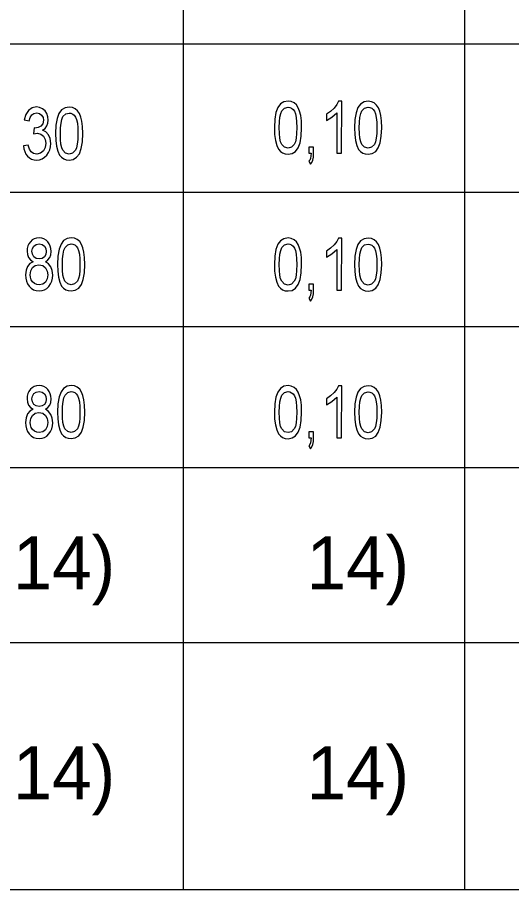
# Model space of a CAD drawing. Extents: x -480568.5 to -480543.1, y -1126945.4 to -1126930.6.
# Drawn here: x -480548.039 to -480547.136, y -1126935.259 to -1126933.667 of the extents above; entities that cross this region are included whole.
import ezdxf

# ---------------------------------------------------------------- set-up
doc = ezdxf.new("R2010")
doc.units = 0
doc.layers.add('detaily', color=7, linetype='Continuous')
doc.layers.add('EL1', color=7, linetype='Continuous')

msp = doc.modelspace()

# ---------------------------------------------------------------- linework, layer by layer
at = {"layer": 'detaily'}
msp.add_lwpolyline([(-480551.8459, -1126935.2592), (-480543.5956, -1126935.2592), (-480543.5956, -1126932.0257), (-480551.8459, -1126932.0257)], close=True, dxfattribs=at)
at = {"layer": 'EL1'}
for p, q in [((-480547.222, -1126932.0257), (-480547.222, -1126935.2588)), ((-480547.7355, -1126935.2588), (-480547.7355, -1126932.3243)), ((-480550.8407, -1126933.7155), (-480543.5956, -1126933.7155)), ((-480549.8036, -1126933.9862), (-480543.5956, -1126933.9862)), ((-480550.8351, -1126934.2311), (-480543.5956, -1126934.2311)), ((-480543.5956, -1126934.4894), (-480551.8459, -1126934.4894)), ((-480543.5956, -1126934.8085), (-480551.8459, -1126934.8085))]:
    msp.add_line(p, q, dxfattribs=at)
for points in [[(-480547.5692, -1126933.8683), (-480547.5688, -1126933.8808), (-480547.5674, -1126933.8915), (-480547.565, -1126933.9006), (-480547.5617, -1126933.9078), (-480547.5583, -1126933.9117), (-480547.5543, -1126933.9145), (-480547.5497, -1126933.9162), (-480547.5444, -1126933.9167), (-480547.5368, -1126933.9154), (-480547.5306, -1126933.9116), (-480547.5258, -1126933.9051), (-480547.5223, -1126933.8958), (-480547.5203, -1126933.8836), (-480547.5195, -1126933.8684), (-480547.5199, -1126933.8557), (-480547.5212, -1126933.846), (-480547.5232, -1126933.8383), (-480547.5256, -1126933.8319), (-480547.5288, -1126933.8268), (-480547.5332, -1126933.823), (-480547.5385, -1126933.8207), (-480547.5443, -1126933.8199), (-480547.5519, -1126933.8212), (-480547.5581, -1126933.825), (-480547.5629, -1126933.8315), (-480547.5664, -1126933.8408), (-480547.5685, -1126933.853)], [(-480547.4464, -1126933.915), (-480547.4463, -1126933.82), (-480547.452, -1126933.82), (-480547.4553, -1126933.8263), (-480547.4603, -1126933.8327), (-480547.4667, -1126933.8387), (-480547.4741, -1126933.8437), (-480547.4741, -1126933.855), (-480547.4641, -1126933.849), (-480547.4551, -1126933.841), (-480547.4552, -1126933.915)], [(-480547.4229, -1126933.8685), (-480547.4225, -1126933.881), (-480547.4211, -1126933.8917), (-480547.4188, -1126933.9008), (-480547.4155, -1126933.908), (-480547.4121, -1126933.9119), (-480547.408, -1126933.9147), (-480547.4034, -1126933.9164), (-480547.3982, -1126933.9169), (-480547.3905, -1126933.9156), (-480547.3843, -1126933.9118), (-480547.3795, -1126933.9053), (-480547.376, -1126933.896), (-480547.374, -1126933.8838), (-480547.3732, -1126933.8686), (-480547.3737, -1126933.8559), (-480547.3749, -1126933.8462), (-480547.3769, -1126933.8385), (-480547.3793, -1126933.832), (-480547.3825, -1126933.827), (-480547.3869, -1126933.8232), (-480547.3922, -1126933.8209), (-480547.398, -1126933.8201), (-480547.4056, -1126933.8214), (-480547.4118, -1126933.8252), (-480547.4167, -1126933.8317), (-480547.4201, -1126933.841), (-480547.4222, -1126933.8532)], [(-480548.0275, -1126933.9018), (-480548.0267, -1126933.9072), (-480548.0252, -1126933.9121), (-480548.023, -1126933.9165), (-480548.02, -1126933.9203), (-480548.0165, -1126933.9234), (-480548.0126, -1126933.9256), (-480548.0082, -1126933.927), (-480548.0034, -1126933.9274), (-480547.9982, -1126933.9269), (-480547.9934, -1126933.9252), (-480547.989, -1126933.9225), (-480547.9851, -1126933.9186), (-480547.982, -1126933.9139), (-480547.9797, -1126933.9088), (-480547.9783, -1126933.9031), (-480547.9778, -1126933.897), (-480547.9788, -1126933.8884), (-480547.9819, -1126933.8813), (-480547.9866, -1126933.8761), (-480547.9926, -1126933.873), (-480547.9881, -1126933.8696), (-480547.9848, -1126933.8653), (-480547.9828, -1126933.8601), (-480547.9822, -1126933.8544), (-480547.9828, -1126933.8484), (-480547.9848, -1126933.8426), (-480547.9881, -1126933.8377), (-480547.9926, -1126933.8338), (-480547.998, -1126933.8314), (-480548.0038, -1126933.8306), (-480548.0118, -1126933.8321), (-480548.0184, -1126933.8368), (-480548.0233, -1126933.8443), (-480548.026, -1126933.8543), (-480548.0172, -1126933.8561), (-480548.0155, -1126933.8498), (-480548.0125, -1126933.8452), (-480548.0084, -1126933.8425), (-480548.0034, -1126933.8415), (-480547.9984, -1126933.8425), (-480547.9944, -1126933.8453), (-480547.9918, -1126933.8496), (-480547.9909, -1126933.8549), (-480547.9922, -1126933.8612), (-480547.9957, -1126933.8656), (-480548.0008, -1126933.8682), (-480548.0065, -1126933.8691), (-480548.0081, -1126933.8689), (-480548.0092, -1126933.8799), (-480548.0022, -1126933.8786), (-480547.996, -1126933.88), (-480547.991, -1126933.8838), (-480547.9877, -1126933.8897), (-480547.9866, -1126933.8969), (-480547.9877, -1126933.9045), (-480547.991, -1126933.9108), (-480547.9963, -1126933.9151), (-480548.0031, -1126933.9165), (-480548.009, -1126933.9155), (-480548.0134, -1126933.9126), (-480548.0166, -1126933.9075), (-480548.0188, -1126933.9)], [(-480547.969, -1126933.8791), (-480547.9685, -1126933.8916), (-480547.9671, -1126933.9023), (-480547.9648, -1126933.9113), (-480547.9615, -1126933.9186), (-480547.9581, -1126933.9225), (-480547.9541, -1126933.9253), (-480547.9494, -1126933.9269), (-480547.9442, -1126933.9275), (-480547.9366, -1126933.9262), (-480547.9304, -1126933.9224), (-480547.9255, -1126933.9159), (-480547.9221, -1126933.9065), (-480547.92, -1126933.8943), (-480547.9193, -1126933.8791), (-480547.9197, -1126933.8665), (-480547.921, -1126933.8567), (-480547.9229, -1126933.8491), (-480547.9253, -1126933.8426), (-480547.9286, -1126933.8375), (-480547.933, -1126933.8338), (-480547.9382, -1126933.8314), (-480547.9441, -1126933.8307), (-480547.9517, -1126933.8319), (-480547.9579, -1126933.8357), (-480547.9627, -1126933.8423), (-480547.9662, -1126933.8516), (-480547.9683, -1126933.8638)], [(-480547.9602, -1126933.8791), (-480547.9599, -1126933.8687), (-480547.959, -1126933.8601), (-480547.9575, -1126933.8533), (-480547.9554, -1126933.8482), (-480547.9504, -1126933.8433), (-480547.9442, -1126933.8416), (-480547.9408, -1126933.8421), (-480547.9376, -1126933.8435), (-480547.9349, -1126933.8458), (-480547.9325, -1126933.8491), (-480547.9306, -1126933.8537), (-480547.9291, -1126933.8603), (-480547.9283, -1126933.8688), (-480547.9281, -1126933.8791), (-480547.9284, -1126933.8898), (-480547.9292, -1126933.8984), (-480547.9307, -1126933.905), (-480547.9327, -1126933.9095), (-480547.9379, -1126933.9148), (-480547.9442, -1126933.9165), (-480547.9505, -1126933.9148), (-480547.9556, -1126933.9095), (-480547.9577, -1126933.905), (-480547.9591, -1126933.8984), (-480547.9599, -1126933.8898)], [(-480547.5604, -1126933.8683), (-480547.5602, -1126933.8579), (-480547.5593, -1126933.8493), (-480547.5578, -1126933.8425), (-480547.5557, -1126933.8374), (-480547.5507, -1126933.8325), (-480547.5444, -1126933.8309), (-480547.541, -1126933.8314), (-480547.5379, -1126933.8327), (-480547.5351, -1126933.8351), (-480547.5327, -1126933.8383), (-480547.5308, -1126933.843), (-480547.5294, -1126933.8495), (-480547.5286, -1126933.858), (-480547.5283, -1126933.8683), (-480547.5286, -1126933.879), (-480547.5295, -1126933.8877), (-480547.531, -1126933.8943), (-480547.533, -1126933.8988), (-480547.5382, -1126933.904), (-480547.5444, -1126933.9058), (-480547.5507, -1126933.904), (-480547.5559, -1126933.8988), (-480547.5579, -1126933.8942), (-480547.5593, -1126933.8876), (-480547.5602, -1126933.879)], [(-480547.4142, -1126933.8685), (-480547.4139, -1126933.8581), (-480547.413, -1126933.8495), (-480547.4115, -1126933.8427), (-480547.4094, -1126933.8376), (-480547.4044, -1126933.8327), (-480547.3982, -1126933.831), (-480547.3947, -1126933.8315), (-480547.3916, -1126933.8329), (-480547.3888, -1126933.8353), (-480547.3864, -1126933.8385), (-480547.3845, -1126933.8432), (-480547.3831, -1126933.8497), (-480547.3823, -1126933.8582), (-480547.382, -1126933.8685), (-480547.3823, -1126933.8792), (-480547.3832, -1126933.8878), (-480547.3847, -1126933.8944), (-480547.3867, -1126933.899), (-480547.3919, -1126933.9042), (-480547.3981, -1126933.906), (-480547.4044, -1126933.9042), (-480547.4096, -1126933.8989), (-480547.4116, -1126933.8944), (-480547.4131, -1126933.8878), (-480547.4139, -1126933.8792)], [(-480547.5064, -1126933.9149), (-480547.502, -1126933.915), (-480547.5032, -1126933.9245), (-480547.5045, -1126933.9274), (-480547.5064, -1126933.9296), (-480547.5035, -1126933.935), (-480547.5009, -1126933.9319), (-480547.499, -1126933.9276), (-480547.498, -1126933.922), (-480547.4976, -1126933.915), (-480547.4976, -1126933.904), (-480547.5064, -1126933.904)], [(-480548.0101, -1126934.113), (-480548.0159, -1126934.1162), (-480548.0203, -1126934.1215), (-480548.0229, -1126934.1285), (-480548.0238, -1126934.1371), (-480548.0234, -1126934.1431), (-480548.0221, -1126934.1485), (-480548.02, -1126934.1535), (-480548.017, -1126934.1579), (-480548.0134, -1126934.1616), (-480548.0091, -1126934.1642), (-480548.0044, -1126934.1658), (-480547.999, -1126934.1663), (-480547.9937, -1126934.1658), (-480547.9889, -1126934.1642), (-480547.9847, -1126934.1617), (-480547.981, -1126934.158), (-480547.978, -1126934.1536), (-480547.9759, -1126934.1487), (-480547.9746, -1126934.1433), (-480547.9741, -1126934.1375), (-480547.975, -1126934.1292), (-480547.9775, -1126934.1222), (-480547.9818, -1126934.1167), (-480547.9875, -1126934.113), (-480547.9829, -1126934.1098), (-480547.9796, -1126934.1055), (-480547.9777, -1126934.1002), (-480547.977, -1126934.0941), (-480547.9774, -1126934.0892), (-480547.9785, -1126934.0846), (-480547.9804, -1126934.0804), (-480547.983, -1126934.0766), (-480547.9863, -1126934.0735), (-480547.9901, -1126934.0713), (-480547.9943, -1126934.0699), (-480547.999, -1126934.0695), (-480548.0038, -1126934.0699), (-480548.008, -1126934.0712), (-480548.0117, -1126934.0734), (-480548.0149, -1126934.0765), (-480548.0175, -1126934.0802), (-480548.0194, -1126934.0843), (-480548.0205, -1126934.0888), (-480548.0209, -1126934.0937), (-480548.0202, -1126934.1001), (-480548.0182, -1126934.1054), (-480548.0149, -1126934.1098)], [(-480548.0121, -1126934.0937), (-480548.0112, -1126934.0887), (-480548.0087, -1126934.0844), (-480548.0046, -1126934.0814), (-480547.9989, -1126934.0804), (-480547.9933, -1126934.0815), (-480547.9892, -1126934.0845), (-480547.9866, -1126934.089), (-480547.9858, -1126934.0944), (-480547.9866, -1126934.0996), (-480547.9891, -1126934.104), (-480547.9932, -1126934.1069), (-480547.9988, -1126934.1078), (-480548.0046, -1126934.1069), (-480548.0088, -1126934.1039), (-480548.0113, -1126934.0994)], [(-480547.9653, -1126934.1179), (-480547.9648, -1126934.1304), (-480547.9634, -1126934.1412), (-480547.9611, -1126934.1502), (-480547.9578, -1126934.1574), (-480547.9544, -1126934.1613), (-480547.9504, -1126934.1641), (-480547.9457, -1126934.1658), (-480547.9405, -1126934.1664), (-480547.9329, -1126934.1651), (-480547.9267, -1126934.1612), (-480547.9218, -1126934.1547), (-480547.9184, -1126934.1454), (-480547.9163, -1126934.1332), (-480547.9156, -1126934.118), (-480547.916, -1126934.1054), (-480547.9173, -1126934.0956), (-480547.9192, -1126934.0879), (-480547.9216, -1126934.0815), (-480547.9249, -1126934.0764), (-480547.9293, -1126934.0726), (-480547.9345, -1126934.0703), (-480547.9404, -1126934.0695), (-480547.948, -1126934.0708), (-480547.9542, -1126934.0746), (-480547.959, -1126934.0812), (-480547.9625, -1126934.0904), (-480547.9646, -1126934.1027)], [(-480547.9565, -1126934.1179), (-480547.9562, -1126934.1076), (-480547.9553, -1126934.099), (-480547.9538, -1126934.0922), (-480547.9517, -1126934.0871), (-480547.9467, -1126934.0822), (-480547.9405, -1126934.0805), (-480547.9371, -1126934.081), (-480547.9339, -1126934.0824), (-480547.9312, -1126934.0847), (-480547.9288, -1126934.0879), (-480547.9269, -1126934.0926), (-480547.9254, -1126934.0992), (-480547.9246, -1126934.1076), (-480547.9244, -1126934.118), (-480547.9247, -1126934.1287), (-480547.9255, -1126934.1373), (-480547.927, -1126934.1439), (-480547.929, -1126934.1484), (-480547.9342, -1126934.1537), (-480547.9405, -1126934.1554), (-480547.9468, -1126934.1537), (-480547.9519, -1126934.1484), (-480547.954, -1126934.1439), (-480547.9554, -1126934.1373), (-480547.9562, -1126934.1287)], [(-480547.5692, -1126934.1181), (-480547.5688, -1126934.1306), (-480547.5674, -1126934.1414), (-480547.565, -1126934.1504), (-480547.5617, -1126934.1576), (-480547.5583, -1126934.1615), (-480547.5543, -1126934.1643), (-480547.5497, -1126934.166), (-480547.5444, -1126934.1665), (-480547.5368, -1126934.1653), (-480547.5306, -1126934.1614), (-480547.5258, -1126934.1549), (-480547.5223, -1126934.1456), (-480547.5203, -1126934.1334), (-480547.5195, -1126934.1182), (-480547.5199, -1126934.1056), (-480547.5212, -1126934.0958), (-480547.5232, -1126934.0881), (-480547.5256, -1126934.0817), (-480547.5288, -1126934.0766), (-480547.5332, -1126934.0728), (-480547.5385, -1126934.0705), (-480547.5443, -1126934.0697), (-480547.5519, -1126934.071), (-480547.5581, -1126934.0748), (-480547.5629, -1126934.0813), (-480547.5664, -1126934.0906), (-480547.5685, -1126934.1029)], [(-480547.5604, -1126934.1181), (-480547.5602, -1126934.1077), (-480547.5593, -1126934.0992), (-480547.5578, -1126934.0923), (-480547.5557, -1126934.0872), (-480547.5507, -1126934.0823), (-480547.5444, -1126934.0807), (-480547.541, -1126934.0812), (-480547.5379, -1126934.0825), (-480547.5351, -1126934.0849), (-480547.5327, -1126934.0881), (-480547.5308, -1126934.0928), (-480547.5294, -1126934.0993), (-480547.5286, -1126934.1078), (-480547.5283, -1126934.1182), (-480547.5286, -1126934.1289), (-480547.5295, -1126934.1375), (-480547.531, -1126934.1441), (-480547.533, -1126934.1486), (-480547.5382, -1126934.1539), (-480547.5444, -1126934.1556), (-480547.5507, -1126934.1538), (-480547.5559, -1126934.1486), (-480547.5579, -1126934.1441), (-480547.5593, -1126934.1375), (-480547.5602, -1126934.1288)], [(-480547.4464, -1126934.1648), (-480547.4463, -1126934.0698), (-480547.452, -1126934.0698), (-480547.4553, -1126934.0761), (-480547.4603, -1126934.0825), (-480547.4667, -1126934.0885), (-480547.4741, -1126934.0936), (-480547.4741, -1126934.1048), (-480547.4641, -1126934.0988), (-480547.4551, -1126934.0908), (-480547.4552, -1126934.1648)], [(-480547.4229, -1126934.1183), (-480547.4225, -1126934.1308), (-480547.4211, -1126934.1416), (-480547.4188, -1126934.1506), (-480547.4155, -1126934.1578), (-480547.4121, -1126934.1617), (-480547.408, -1126934.1645), (-480547.4034, -1126934.1662), (-480547.3982, -1126934.1667), (-480547.3905, -1126934.1654), (-480547.3843, -1126934.1616), (-480547.3795, -1126934.1551), (-480547.376, -1126934.1458), (-480547.374, -1126934.1336), (-480547.3732, -1126934.1184), (-480547.3737, -1126934.1057), (-480547.3749, -1126934.096), (-480547.3769, -1126934.0883), (-480547.3793, -1126934.0819), (-480547.3825, -1126934.0768), (-480547.3869, -1126934.073), (-480547.3922, -1126934.0707), (-480547.398, -1126934.0699), (-480547.4056, -1126934.0712), (-480547.4118, -1126934.075), (-480547.4167, -1126934.0815), (-480547.4201, -1126934.0908), (-480547.4222, -1126934.103)], [(-480547.4142, -1126934.1183), (-480547.4139, -1126934.1079), (-480547.413, -1126934.0993), (-480547.4115, -1126934.0925), (-480547.4094, -1126934.0874), (-480547.4044, -1126934.0825), (-480547.3982, -1126934.0809), (-480547.3947, -1126934.0814), (-480547.3916, -1126934.0827), (-480547.3888, -1126934.0851), (-480547.3864, -1126934.0883), (-480547.3845, -1126934.093), (-480547.3831, -1126934.0995), (-480547.3823, -1126934.108), (-480547.382, -1126934.1183), (-480547.3823, -1126934.129), (-480547.3832, -1126934.1377), (-480547.3847, -1126934.1443), (-480547.3867, -1126934.1488), (-480547.3919, -1126934.154), (-480547.3981, -1126934.1558), (-480547.4044, -1126934.154), (-480547.4096, -1126934.1488), (-480547.4116, -1126934.1442), (-480547.4131, -1126934.1376), (-480547.4139, -1126934.129)], [(-480548.0151, -1126934.1369), (-480548.014, -1126934.1298), (-480548.0109, -1126934.1239), (-480548.0059, -1126934.1201), (-480547.9992, -1126934.1188), (-480547.9923, -1126934.1201), (-480547.9872, -1126934.124), (-480547.984, -1126934.13), (-480547.9829, -1126934.1372), (-480547.984, -1126934.1444), (-480547.9871, -1126934.1502), (-480547.9921, -1126934.1541), (-480547.9989, -1126934.1553), (-480548.0033, -1126934.1547), (-480548.0076, -1126934.1529), (-480548.0112, -1126934.15), (-480548.0135, -1126934.146), (-480548.0147, -1126934.1415)], [(-480547.5064, -1126934.1648), (-480547.502, -1126934.1648), (-480547.5032, -1126934.1744), (-480547.5045, -1126934.1773), (-480547.5064, -1126934.1794), (-480547.5035, -1126934.1849), (-480547.5009, -1126934.1817), (-480547.499, -1126934.1774), (-480547.498, -1126934.1718), (-480547.4976, -1126934.1648), (-480547.4976, -1126934.1538), (-480547.5064, -1126934.1538)], [(-480548.0101, -1126934.3825), (-480548.0159, -1126934.3858), (-480548.0203, -1126934.391), (-480548.0229, -1126934.3981), (-480548.0238, -1126934.4066), (-480548.0234, -1126934.4126), (-480548.0221, -1126934.4181), (-480548.02, -1126934.4231), (-480548.017, -1126934.4275), (-480548.0134, -1126934.4311), (-480548.0091, -1126934.4337), (-480548.0044, -1126934.4353), (-480547.999, -1126934.4358), (-480547.9937, -1126934.4353), (-480547.9889, -1126934.4338), (-480547.9847, -1126934.4312), (-480547.981, -1126934.4275), (-480547.978, -1126934.4232), (-480547.9759, -1126934.4183), (-480547.9746, -1126934.4129), (-480547.9741, -1126934.407), (-480547.975, -1126934.3988), (-480547.9775, -1126934.3918), (-480547.9818, -1126934.3863), (-480547.9875, -1126934.3825), (-480547.9829, -1126934.3794), (-480547.9796, -1126934.3751), (-480547.9777, -1126934.3698), (-480547.977, -1126934.3636), (-480547.9774, -1126934.3587), (-480547.9785, -1126934.3542), (-480547.9804, -1126934.35), (-480547.983, -1126934.3462), (-480547.9863, -1126934.3431), (-480547.9901, -1126934.3408), (-480547.9943, -1126934.3395), (-480547.999, -1126934.339), (-480548.0038, -1126934.3395), (-480548.008, -1126934.3408), (-480548.0117, -1126934.343), (-480548.0149, -1126934.346), (-480548.0175, -1126934.3497), (-480548.0194, -1126934.3538), (-480548.0205, -1126934.3584), (-480548.0209, -1126934.3633), (-480548.0202, -1126934.3696), (-480548.0182, -1126934.375), (-480548.0149, -1126934.3793)], [(-480547.9653, -1126934.3875), (-480547.9648, -1126934.4), (-480547.9634, -1126934.4107), (-480547.9611, -1126934.4198), (-480547.9578, -1126934.427), (-480547.9544, -1126934.4309), (-480547.9504, -1126934.4337), (-480547.9457, -1126934.4353), (-480547.9405, -1126934.4359), (-480547.9329, -1126934.4346), (-480547.9267, -1126934.4308), (-480547.9218, -1126934.4243), (-480547.9184, -1126934.415), (-480547.9163, -1126934.4028), (-480547.9156, -1126934.3875), (-480547.916, -1126934.3749), (-480547.9173, -1126934.3651), (-480547.9192, -1126934.3575), (-480547.9216, -1126934.351), (-480547.9249, -1126934.346), (-480547.9293, -1126934.3422), (-480547.9345, -1126934.3399), (-480547.9404, -1126934.3391), (-480547.948, -1126934.3404), (-480547.9542, -1126934.3442), (-480547.959, -1126934.3507), (-480547.9625, -1126934.36), (-480547.9646, -1126934.3722)], [(-480548.0121, -1126934.3633), (-480548.0112, -1126934.3582), (-480548.0087, -1126934.3539), (-480548.0046, -1126934.351), (-480547.9989, -1126934.35), (-480547.9933, -1126934.351), (-480547.9892, -1126934.354), (-480547.9866, -1126934.3585), (-480547.9858, -1126934.3639), (-480547.9866, -1126934.3692), (-480547.9891, -1126934.3735), (-480547.9932, -1126934.3764), (-480547.9988, -1126934.3774), (-480548.0046, -1126934.3764), (-480548.0088, -1126934.3734), (-480548.0113, -1126934.3689)], [(-480547.9565, -1126934.3875), (-480547.9562, -1126934.3771), (-480547.9553, -1126934.3685), (-480547.9538, -1126934.3617), (-480547.9517, -1126934.3566), (-480547.9467, -1126934.3517), (-480547.9405, -1126934.35), (-480547.9371, -1126934.3505), (-480547.9339, -1126934.3519), (-480547.9312, -1126934.3542), (-480547.9288, -1126934.3575), (-480547.9269, -1126934.3622), (-480547.9254, -1126934.3687), (-480547.9246, -1126934.3772), (-480547.9244, -1126934.3875), (-480547.9247, -1126934.3982), (-480547.9255, -1126934.4068), (-480547.927, -1126934.4134), (-480547.929, -1126934.4179), (-480547.9342, -1126934.4232), (-480547.9405, -1126934.4249), (-480547.9468, -1126934.4232), (-480547.9519, -1126934.4179), (-480547.954, -1126934.4134), (-480547.9554, -1126934.4068), (-480547.9562, -1126934.3982)], [(-480547.5692, -1126934.3877), (-480547.5688, -1126934.4002), (-480547.5674, -1126934.4109), (-480547.565, -1126934.4199), (-480547.5617, -1126934.4272), (-480547.5583, -1126934.4311), (-480547.5543, -1126934.4339), (-480547.5497, -1126934.4355), (-480547.5444, -1126934.4361), (-480547.5368, -1126934.4348), (-480547.5306, -1126934.431), (-480547.5258, -1126934.4245), (-480547.5223, -1126934.4151), (-480547.5203, -1126934.403), (-480547.5195, -1126934.3877), (-480547.5199, -1126934.3751), (-480547.5212, -1126934.3653), (-480547.5232, -1126934.3577), (-480547.5256, -1126934.3512), (-480547.5288, -1126934.3461), (-480547.5332, -1126934.3424), (-480547.5385, -1126934.34), (-480547.5443, -1126934.3393), (-480547.5519, -1126934.3405), (-480547.5581, -1126934.3444), (-480547.5629, -1126934.3509), (-480547.5664, -1126934.3602), (-480547.5685, -1126934.3724)], [(-480547.5604, -1126934.3877), (-480547.5602, -1126934.3773), (-480547.5593, -1126934.3687), (-480547.5578, -1126934.3619), (-480547.5557, -1126934.3568), (-480547.5507, -1126934.3519), (-480547.5444, -1126934.3502), (-480547.541, -1126934.3507), (-480547.5379, -1126934.3521), (-480547.5351, -1126934.3544), (-480547.5327, -1126934.3577), (-480547.5308, -1126934.3623), (-480547.5294, -1126934.3689), (-480547.5286, -1126934.3774), (-480547.5283, -1126934.3877), (-480547.5286, -1126934.3984), (-480547.5295, -1126934.407), (-480547.531, -1126934.4136), (-480547.533, -1126934.4181), (-480547.5382, -1126934.4234), (-480547.5444, -1126934.4251), (-480547.5507, -1126934.4234), (-480547.5559, -1126934.4181), (-480547.5579, -1126934.4136), (-480547.5593, -1126934.407), (-480547.5602, -1126934.3984)], [(-480547.4464, -1126934.4344), (-480547.4463, -1126934.3394), (-480547.452, -1126934.3394), (-480547.4553, -1126934.3456), (-480547.4603, -1126934.352), (-480547.4667, -1126934.3581), (-480547.4741, -1126934.3631), (-480547.4741, -1126934.3743), (-480547.4641, -1126934.3683), (-480547.4551, -1126934.3604), (-480547.4552, -1126934.4344)], [(-480547.4229, -1126934.3879), (-480547.4225, -1126934.4004), (-480547.4211, -1126934.4111), (-480547.4188, -1126934.4201), (-480547.4155, -1126934.4274), (-480547.4121, -1126934.4313), (-480547.408, -1126934.434), (-480547.4034, -1126934.4357), (-480547.3982, -1126934.4363), (-480547.3905, -1126934.435), (-480547.3843, -1126934.4312), (-480547.3795, -1126934.4247), (-480547.376, -1126934.4153), (-480547.374, -1126934.4031), (-480547.3732, -1126934.3879), (-480547.3737, -1126934.3753), (-480547.3749, -1126934.3655), (-480547.3769, -1126934.3579), (-480547.3793, -1126934.3514), (-480547.3825, -1126934.3463), (-480547.3869, -1126934.3425), (-480547.3922, -1126934.3402), (-480547.398, -1126934.3394), (-480547.4056, -1126934.3407), (-480547.4118, -1126934.3445), (-480547.4167, -1126934.3511), (-480547.4201, -1126934.3603), (-480547.4222, -1126934.3726)], [(-480547.4142, -1126934.3878), (-480547.4139, -1126934.3775), (-480547.413, -1126934.3689), (-480547.4115, -1126934.3621), (-480547.4094, -1126934.357), (-480547.4044, -1126934.3521), (-480547.3982, -1126934.3504), (-480547.3947, -1126934.3509), (-480547.3916, -1126934.3523), (-480547.3888, -1126934.3546), (-480547.3864, -1126934.3578), (-480547.3845, -1126934.3625), (-480547.3831, -1126934.3691), (-480547.3823, -1126934.3775), (-480547.382, -1126934.3879), (-480547.3823, -1126934.3986), (-480547.3832, -1126934.4072), (-480547.3847, -1126934.4138), (-480547.3867, -1126934.4183), (-480547.3919, -1126934.4236), (-480547.3981, -1126934.4253), (-480547.4044, -1126934.4236), (-480547.4096, -1126934.4183), (-480547.4116, -1126934.4138), (-480547.4131, -1126934.4072), (-480547.4139, -1126934.3986)], [(-480548.0151, -1126934.4064), (-480548.014, -1126934.3993), (-480548.0109, -1126934.3935), (-480548.0059, -1126934.3896), (-480547.9992, -1126934.3883), (-480547.9923, -1126934.3896), (-480547.9872, -1126934.3936), (-480547.984, -1126934.3995), (-480547.9829, -1126934.4068), (-480547.984, -1126934.414), (-480547.9871, -1126934.4198), (-480547.9921, -1126934.4236), (-480547.9989, -1126934.4249), (-480548.0033, -1126934.4243), (-480548.0076, -1126934.4224), (-480548.0112, -1126934.4195), (-480548.0135, -1126934.4156), (-480548.0147, -1126934.4111)], [(-480547.5064, -1126934.4343), (-480547.502, -1126934.4343), (-480547.5032, -1126934.4439), (-480547.5045, -1126934.4468), (-480547.5064, -1126934.4489), (-480547.5035, -1126934.4544), (-480547.5009, -1126934.4512), (-480547.499, -1126934.447), (-480547.498, -1126934.4414), (-480547.4976, -1126934.4343), (-480547.4976, -1126934.4234), (-480547.5064, -1126934.4233)]]:
    msp.add_lwpolyline(points, close=True, dxfattribs=at)

# ---------------------------------------------------------------- texts
for rotation, p in [(0, (-480548.0471, -1126934.7114)), (360, (-480547.5103, -1126934.7114)), (0, (-480548.0471, -1126935.0944)), (0, (-480547.5103, -1126935.0944))]:
    msp.add_text('14)                  ', height=0.096829, rotation=rotation, dxfattribs=at).set_placement(p)

doc.saveas('drawing.dxf')
